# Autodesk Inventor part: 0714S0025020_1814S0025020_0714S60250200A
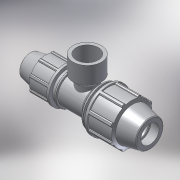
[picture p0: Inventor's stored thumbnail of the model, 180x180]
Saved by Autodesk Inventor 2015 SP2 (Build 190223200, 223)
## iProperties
Created: 2017-02
Part Number: 0714S0025020_1814S0025020_0714S60250200A
Material: PVC-Piping
Description: PLASSON REDUCING TEE FEMALE 25-3/4"-20
Document SubType Name: Modeling
Designer: KIM
Mass: 92.6774 g
Surface Area: 199.44 cm^2
Volume: 66.1981 cm^3
Density: 1.4 g/cm^3
Appearance: Smooth - White
Author: KIM
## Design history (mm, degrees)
derived "0714S0.ipt"
feature "Solid1::0714S0.ipt"
feature "Solid2::0714S0.ipt"
tag "TaggingFeature1"
body "Solid1"
body "Solid2"
other parameters: "d2" = 25, "d4" = 11.58333, "d5" = 19.85714, "d7" = 54, "d9" = 19.85714, "d11" = 1.98571, "d12" = 43.2, "d13" = 120 deg, "d14" = 37.5, "d15" = 12 deg, "d16" = 48.6, "d18" = 1.25, "d19" = 35 deg, "d20" = 17.5 deg, "d21" = 50.22, "d23" = 0, "d25" = 360 deg, "d27" = 1.08, "d42" = 30.58, "d46" = 0.75, "d51" = 139, "d53" = 12 deg, "d54" = 53, "d58" = 22.5, "d59" = 18, "d60" = 43.2, "d61" = 38.4, "d62" = 17.375, "d63" = 25.02, "d64" = 120 deg, "d65" = 48, "d68" = 9.92857, "d74" = 44.64, "d75" = 35 deg, "d76" = 17.5 deg, "d78" = 0, "d80" = 360 deg, "d85" = 0.96, "d88" = 0.4, "d93" = 52, "d107" = 3.2, "d108" = 0, "d109" = 3.2, "d110" = 0, "d112" = 4.17, "d113" = 45 deg, "d114" = 24.117, "d115" = 42, "d116" = 22, "d117" = 18, "d118" = 31.3521, "d119" = 135 deg, "d120" = 3.61755, "d123" = 4.17, "d125" = 0, "d127" = 0, "d_" = 25, "E_" = 54, "H_" = 139, "l_" = 53, "E_1" = 48, "l_1" = 52, "l_2" = 22, "A_" = 42, "Rp_" = 24.117
